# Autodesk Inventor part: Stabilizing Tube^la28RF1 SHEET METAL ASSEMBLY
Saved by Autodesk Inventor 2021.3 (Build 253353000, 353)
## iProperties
Created: 2023-01
Part Number: Stabilizing Tube^la28RF1 SHEET METAL ASSEMBLY
Material: Generic
Document SubType Name: Modeling
Designer: AdminForWorker
Density: 1 g/cm^3
Appearance: Default
Title: Stabilizing Tube^la28RF1 SHEET METAL ASSEMBLY
Author: AdminForWorker
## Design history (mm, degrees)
mirror "Mirror2"
body "Solid1"
